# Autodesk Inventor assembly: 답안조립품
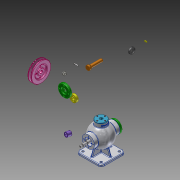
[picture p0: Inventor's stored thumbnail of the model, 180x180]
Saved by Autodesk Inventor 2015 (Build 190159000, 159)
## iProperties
Created: 2025-08
Part Number: 답안조립품
Document SubType Name: Assembly
Designer: USER
Author: USER
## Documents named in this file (15)
- C:\Users\USER\Desktop\750808V1008\답안조립품.iam
- C:\Users\USER\Desktop\750808V1008\본체.ipt
- C:\Users\USER\Desktop\750808V1008\가져온 구성요소\V-벨트풀리\V-벨트풀리.ipt
- C:\Users\USER\Desktop\750808V1008\가져온 구성요소\너트 M8\너트 M8.ipt
- C:\Users\USER\Desktop\750808V1008\가져온 구성요소\뒤커버\뒤커버.ipt
- C:\Users\USER\Desktop\750808V1008\가져온 구성요소\베어링- 6202\베어링- 6202.ipt
- C:\Users\USER\Desktop\750808V1008\가져온 구성요소\볼트 M4 x 12\볼트 M4 x 12.ipt
- C:\Users\USER\Desktop\750808V1008\가져온 구성요소\볼트 M4 x 16\볼트 M4 x 16.ipt
- C:\Users\USER\Desktop\750808V1008\가져온 구성요소\상부커버\상부커버.ipt
- C:\Users\USER\Desktop\750808V1008\가져온 구성요소\슬라이드\슬라이드.ipt
- C:\Users\USER\Desktop\750808V1008\가져온 구성요소\앞커버\앞커버.ipt
- C:\Users\USER\Desktop\750808V1008\가져온 구성요소\오일실 15 30 7\오일실 15 30 7.ipt
- C:\Users\USER\Desktop\750808V1008\가져온 구성요소\칼라\칼라.ipt
- C:\Users\USER\Desktop\750808V1008\가져온 구성요소\키 4 x 4 x 12\키 4 x 4 x 12.ipt
- C:\Users\USER\Desktop\750808V1008\가져온 구성요소\편심축\편심축.ipt
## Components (1 placed, 1 different names)
1. V-벨트풀리:1
